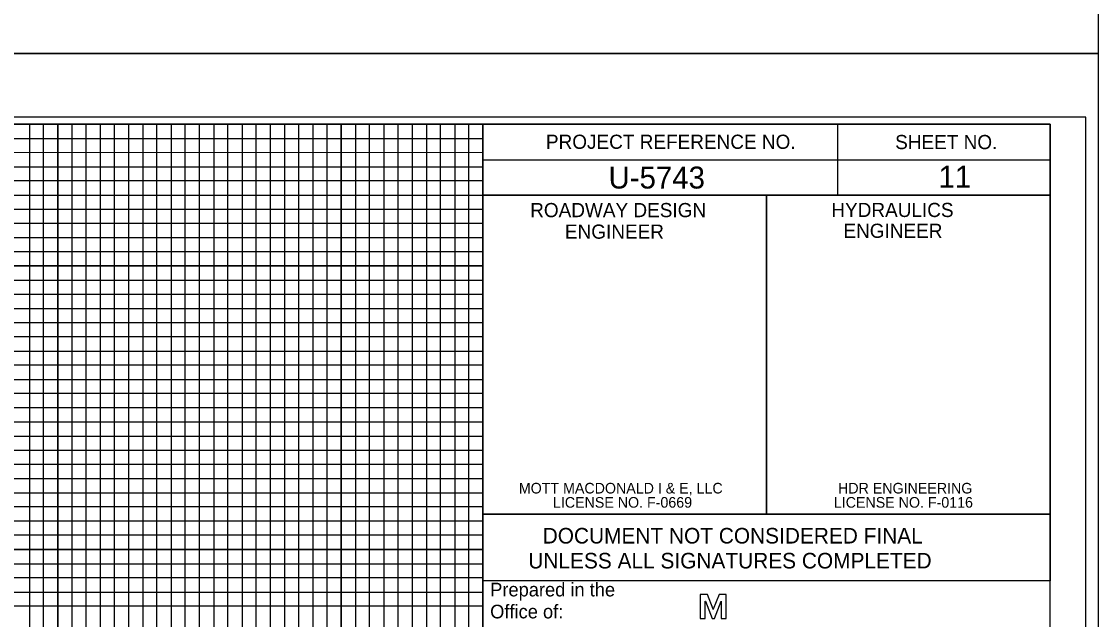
# Model space of a CAD drawing. Extents: x 1755181 to 1757273, y 729911 to 735411.
# Drawn here: x 1756484.9 to 1756864.7, y 731911.1 to 732122 of the extents above; entities that cross this region are included whole.
import ezdxf

# ---------------------------------------------------------------- set-up
doc = ezdxf.new("R2010")
doc.units = 0
for name, color, linetype in [('Old_Level_2', 7, 'Continuous'), ('Old_Level_3', 7, 'Continuous'), ('Old_Level_42', 7, 'Continuous'), ('Old_Level_45', 7, 'Continuous'), ('Scratch_Level_3', 7, 'Continuous'), ('Sheet Cutting Line CELL', 7, 'Continuous'), ('Sheet Data Field CELL', 7, 'Continuous'), ('Sheet DOT Grid CELL', 7, 'Continuous'), ('Sheet Plot Border Inside CELL', 7, 'Continuous'), ('Sheet Plot Border Outside CELL', 7, 'Continuous'), ('Sheet Profile CELL', 7, 'Continuous'), ('Sheet Profile Grid Major CELL', 7, 'Continuous'), ('Sheet Profile Grid Middle CELL', 7, 'Continuous'), ('Sheet Profile Grid Minor CELL', 7, 'Continuous'), ('Sheet Sticker Exception Certification CELL', 7, 'Continuous')]:
    doc.layers.add(name, color=color, linetype=linetype)

msp = doc.modelspace()

# ---------------------------------------------------------------- linework, layer by layer
at = {"layer": 'Old_Level_2'}
for p, q in [((1756726.76, 731919.94), (1756724.24, 731919.94)), ((1756724.24, 731919.94), (1756724.24, 731911.44)), ((1756728.81, 731914.69), (1756726.76, 731919.94)), ((1756730.92, 731919.94), (1756728.86, 731914.69)), ((1756733.44, 731919.94), (1756730.92, 731919.94)), ((1756733.44, 731911.44), (1756733.44, 731919.94)), ((1756726.03, 731911.44), (1756726.03, 731917.55)), ((1756726.03, 731917.55), (1756726.05, 731917.55)), ((1756726.05, 731917.55), (1756728.45, 731911.44)), ((1756729.23, 731911.44), (1756731.62, 731917.57)), ((1756731.62, 731917.57), (1756731.64, 731917.57)), ((1756731.64, 731917.57), (1756731.64, 731911.44)), ((1756724.24, 731911.44), (1756726.03, 731911.44)), ((1756728.45, 731911.44), (1756729.23, 731911.44)), ((1756728.81, 731914.61), (1756728.81, 731914.69)), ((1756728.86, 731914.61), (1756728.81, 731914.61)), ((1756728.86, 731914.69), (1756728.86, 731914.61)), ((1756731.64, 731911.44), (1756733.44, 731911.44))]:
    msp.add_line(p, q, dxfattribs=at)
at = {"layer": 'Old_Level_42'}
msp.add_line((1756647.62, 731924.73), (1756647.62, 731948.23), dxfattribs=at)
msp.add_lwpolyline([(1756847.67, 731889.43), (1756647.62, 731889.43), (1756647.62, 731924.73)], dxfattribs=at)
at = {"layer": 'Scratch_Level_3'}
msp.add_lwpolyline([(1756097.67, 731560.78), (1756097.67, 732085.78), (1756647.63, 732085.78), (1756647.63, 731852.66), (1756847.68, 731852.66), (1756847.68, 731560.78)], close=True, dxfattribs=at)
at = {"layer": 'Sheet Cutting Line CELL'}
msp.add_line((1755180.67, 732110.78), (1756864.67, 732110.78), dxfattribs=at)
at = {"layer": 'Sheet DOT Grid CELL'}
for p, q in [((1756497.67, 731585.78), (1756497.67, 732085.78)), ((1756547.67, 731585.78), (1756547.67, 732085.78)), ((1756597.67, 731585.78), (1756597.67, 732085.78)), ((1756647.62, 732035.78), (1756147.67, 732035.78)), ((1756647.62, 731985.78), (1756147.67, 731985.78)), ((1756647.67, 731585.78), (1756647.67, 731948.23)), ((1756647.67, 731935.78), (1756147.67, 731935.78))]:
    msp.add_line(p, q, dxfattribs=at)
at = {"layer": 'Sheet Plot Border Inside CELL'}
msp.add_lwpolyline([(1755193.67, 731033.23), (1756860.17, 731033.23), (1756860.17, 732088.33), (1755193.67, 732088.33)], close=True, dxfattribs=at)
at = {"layer": 'Sheet Plot Border Outside CELL'}
for points in [[(1755180.67, 732110.78), (1756864.67, 732110.78), (1756864.67, 733210.78), (1755180.67, 733210.78)], [(1755180.67, 731010.78), (1756864.67, 731010.78), (1756864.67, 732110.78), (1755180.67, 732110.78)]]:
    msp.add_lwpolyline(points, close=True, dxfattribs=at)
at = {"layer": 'Sheet Profile CELL'}
for p, q in [((1756772.67, 732085.73), (1756772.67, 732060.73)), ((1756647.62, 732073.23), (1756847.67, 732073.23)), ((1756747.67, 732060.73), (1756747.67, 731948.28))]:
    msp.add_line(p, q, dxfattribs=at)
for points in [[(1756847.67, 732085.78), (1755347.67, 732085.78), (1755347.67, 731035.78), (1756847.67, 731035.78)], [(1756647.62, 732085.78), (1756847.67, 732085.78), (1756847.67, 732060.73), (1756647.62, 732060.73)], [(1756647.62, 732060.73), (1756747.67, 732060.73), (1756747.67, 731948.23), (1756647.62, 731948.23)], [(1756747.67, 732060.73), (1756847.67, 732060.73), (1756847.67, 731948.23), (1756747.67, 731948.23)]]:
    msp.add_lwpolyline(points, close=True, dxfattribs=at)
at = {"layer": 'Sheet Profile Grid Major CELL'}
for points in [[(1756097.67, 731585.78), (1756147.67, 731585.78), (1756147.67, 732085.78), (1756197.67, 732085.78), (1756197.67, 731585.78), (1756247.67, 731585.78), (1756247.67, 732085.78), (1756297.67, 732085.78), (1756297.67, 731585.78), (1756347.67, 731585.78), (1756347.67, 732085.78), (1756397.67, 732085.78), (1756397.67, 731585.78), (1756447.67, 731585.78), (1756447.67, 732085.78), (1756497.67, 732085.78), (1756497.67, 731585.78), (1756547.67, 731585.78), (1756547.67, 732085.78), (1756597.67, 732085.78), (1756597.67, 731585.78), (1756647.67, 731585.78), (1756647.67, 732085.78), (1756673.97, 732085.78)], [(1755347.67, 732035.78), (1756647.67, 732035.78)], [(1756647.67, 731985.78), (1755347.67, 731985.78), (1755347.67, 731935.78), (1756647.67, 731935.78)], [(1756797.67, 731852.66), (1756797.67, 731585.78), (1756847.67, 731585.78), (1756847.67, 731935.78)]]:
    msp.add_lwpolyline(points, dxfattribs=at)
at = {"layer": 'Sheet Profile Grid Middle CELL'}
for p, q in [((1756472.67, 732085.78), (1756522.67, 732085.78)), ((1756522.67, 732085.78), (1756522.67, 731585.78)), ((1756572.67, 731585.78), (1756572.67, 732085.78)), ((1756572.67, 732085.78), (1756622.67, 732085.78)), ((1756622.67, 732085.78), (1756622.67, 731585.78)), ((1755347.67, 732060.78), (1756647.62, 732060.78))]:
    msp.add_line(p, q, dxfattribs=at)
msp.add_lwpolyline([(1756647.67, 732010.78), (1755347.67, 732010.78), (1755347.67, 731960.78), (1756647.67, 731960.78)], dxfattribs=at)
at = {"layer": 'Sheet Profile Grid Minor CELL'}
for p, q in [((1756147.67, 732080.78), (1756647.67, 732080.78)), ((1756647.67, 732075.78), (1756147.67, 732075.64)), ((1756147.67, 732070.78), (1756647.67, 732070.78)), ((1756647.62, 731950.78), (1756147.67, 731950.78)), ((1756647.67, 731945.78), (1756147.67, 731945.78)), ((1756647.67, 731940.78), (1756147.67, 731940.78)), ((1756147.67, 731930.78), (1756647.67, 731930.78)), ((1756647.67, 731925.78), (1756147.67, 731925.78)), ((1756147.67, 731920.78), (1756647.62, 731920.78))]:
    msp.add_line(p, q, dxfattribs=at)
for points in [[(1756482.67, 732085.78), (1756487.67, 732085.78), (1756487.67, 731585.78), (1756492.67, 731585.78), (1756492.67, 732085.78), (1756502.67, 732085.78), (1756502.67, 731585.78), (1756507.67, 731585.78), (1756507.67, 732085.78), (1756512.67, 732085.78), (1756512.67, 731585.78), (1756517.67, 731585.78), (1756517.67, 732085.78), (1756527.67, 732085.78), (1756527.67, 731585.78), (1756532.67, 731585.78), (1756532.67, 732085.78), (1756537.67, 732085.78), (1756537.67, 731585.78)], [(1756542.67, 731585.78), (1756542.67, 732085.78), (1756552.67, 732085.78), (1756552.67, 731585.78)], [(1756557.67, 731585.78), (1756557.67, 732085.78), (1756562.67, 732085.78), (1756562.67, 731585.78)], [(1756567.67, 731585.78), (1756567.67, 732085.78), (1756577.67, 732085.78), (1756577.67, 731585.78)], [(1756582.67, 731585.78), (1756582.67, 732085.78), (1756587.67, 732085.78), (1756587.67, 731585.78)], [(1756592.67, 731585.78), (1756592.67, 732085.78), (1756602.67, 732085.78), (1756602.67, 731585.78)], [(1756607.67, 731585.78), (1756607.67, 732085.78), (1756612.67, 732085.78), (1756612.67, 731585.78)], [(1756617.67, 731585.78), (1756617.67, 732085.78), (1756627.67, 732085.78), (1756627.67, 731585.78)], [(1756632.67, 731585.78), (1756632.67, 732085.78), (1756637.67, 732085.78), (1756637.67, 731585.78)], [(1756642.67, 731585.78), (1756642.67, 732085.78), (1756652.67, 732085.78)], [(1756647.67, 732065.78), (1756147.67, 732065.78)], [(1756147.67, 732055.78), (1756647.67, 732055.78)], [(1756647.62, 732050.78), (1756147.67, 732050.78)], [(1756147.67, 732045.78), (1756647.67, 732045.78)], [(1756647.67, 732040.78), (1756147.67, 732040.78)], [(1756147.67, 732030.78), (1756647.67, 732030.78)], [(1756647.67, 732025.78), (1756147.67, 732025.78)], [(1756147.67, 732020.78), (1756647.67, 732020.78)], [(1756647.67, 732015.78), (1756147.67, 732015.78)], [(1756147.67, 732005.78), (1756647.67, 732005.78)], [(1756647.67, 732000.78), (1756147.67, 732000.78)], [(1756147.67, 731995.78), (1756647.67, 731995.78)], [(1756647.67, 731990.78), (1756147.67, 731990.78)], [(1756147.67, 731980.78), (1756647.67, 731980.78)], [(1756647.67, 731975.68), (1756147.67, 731975.68)], [(1756147.67, 731970.78), (1756647.67, 731970.78)], [(1756647.67, 731965.78), (1756147.67, 731965.78)], [(1756147.67, 731955.78), (1756647.67, 731955.78)], [(1756647.62, 731915.78), (1756147.67, 731915.78)]]:
    msp.add_lwpolyline(points, dxfattribs=at)
at = {"layer": 'Sheet Sticker Exception Certification CELL'}
for p, q in [((1756647.62, 731924.73), (1756647.62, 731948.23)), ((1756647.62, 731948.23), (1756847.66, 731948.23)), ((1756847.66, 731948.22), (1756847.66, 731924.72)), ((1756847.66, 731924.73), (1756647.62, 731924.73))]:
    msp.add_line(p, q, dxfattribs=at)

# ---------------------------------------------------------------- texts
at = {"layer": 'Old_Level_2'}
for s, height, p in [('Prepared in the ', 4.8186, (1756650.17, 731919.23)), ('Office of:', 4.819, (1756650.17, 731911.48))]:
    msp.add_text(s, height=height, dxfattribs=at).set_placement(p)
at = {"layer": 'Old_Level_3'}
for s, p in [('HDR ENGINEERING', (1756772.84, 731955.53)), (' LICENSE NO. F-0116', (1756769.97, 731950.53))]:
    msp.add_text(s, height=3.75, rotation=360, dxfattribs=at).set_placement(p)
at = {"layer": 'Old_Level_45'}
for s, p in [('MOTT MACDONALD I & E, LLC', (1756660.28, 731955.53)), (' LICENSE NO. F-0669', (1756670.92, 731950.53))]:
    msp.add_text(s, height=3.75, rotation=360, dxfattribs=at).set_placement(p)
at = {"layer": 'Sheet Data Field CELL'}
for s, p in [('U-5743', (1756691.91, 732063.1)), ('11', (1756808.29, 732063.4))]:
    msp.add_text(s, height=7.75, dxfattribs=at).set_placement(p)
at = {"layer": 'Sheet Profile CELL'}
for s, height, p in [('PROJECT REFERENCE NO.', 5.0001, (1756669.83, 732077.1)), ('SHEET NO.', 5, (1756792.98, 732077)), ('ROADWAY DESIGN', 5.0001, (1756664.28, 732053)), ('HYDRAULICS', 5, (1756770.48, 732053.05)), ('ENGINEER', 5, (1756676.53, 732045.4)), ('ENGINEER', 5, (1756774.73, 732045.7))]:
    msp.add_text(s, height=height, dxfattribs=at).set_placement(p)
at = {"layer": 'Sheet Sticker Exception Certification CELL'}
for s, p in [('DOCUMENT NOT CONSIDERED FINAL', (1756668.69, 731937.89)), ('UNLESS ALL SIGNATURES COMPLETED', (1756663.62, 731929.09))]:
    msp.add_text(s, height=5.5, dxfattribs=at).set_placement(p)

doc.saveas('drawing.dxf')
